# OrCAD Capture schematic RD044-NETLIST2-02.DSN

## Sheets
1 4: size A3
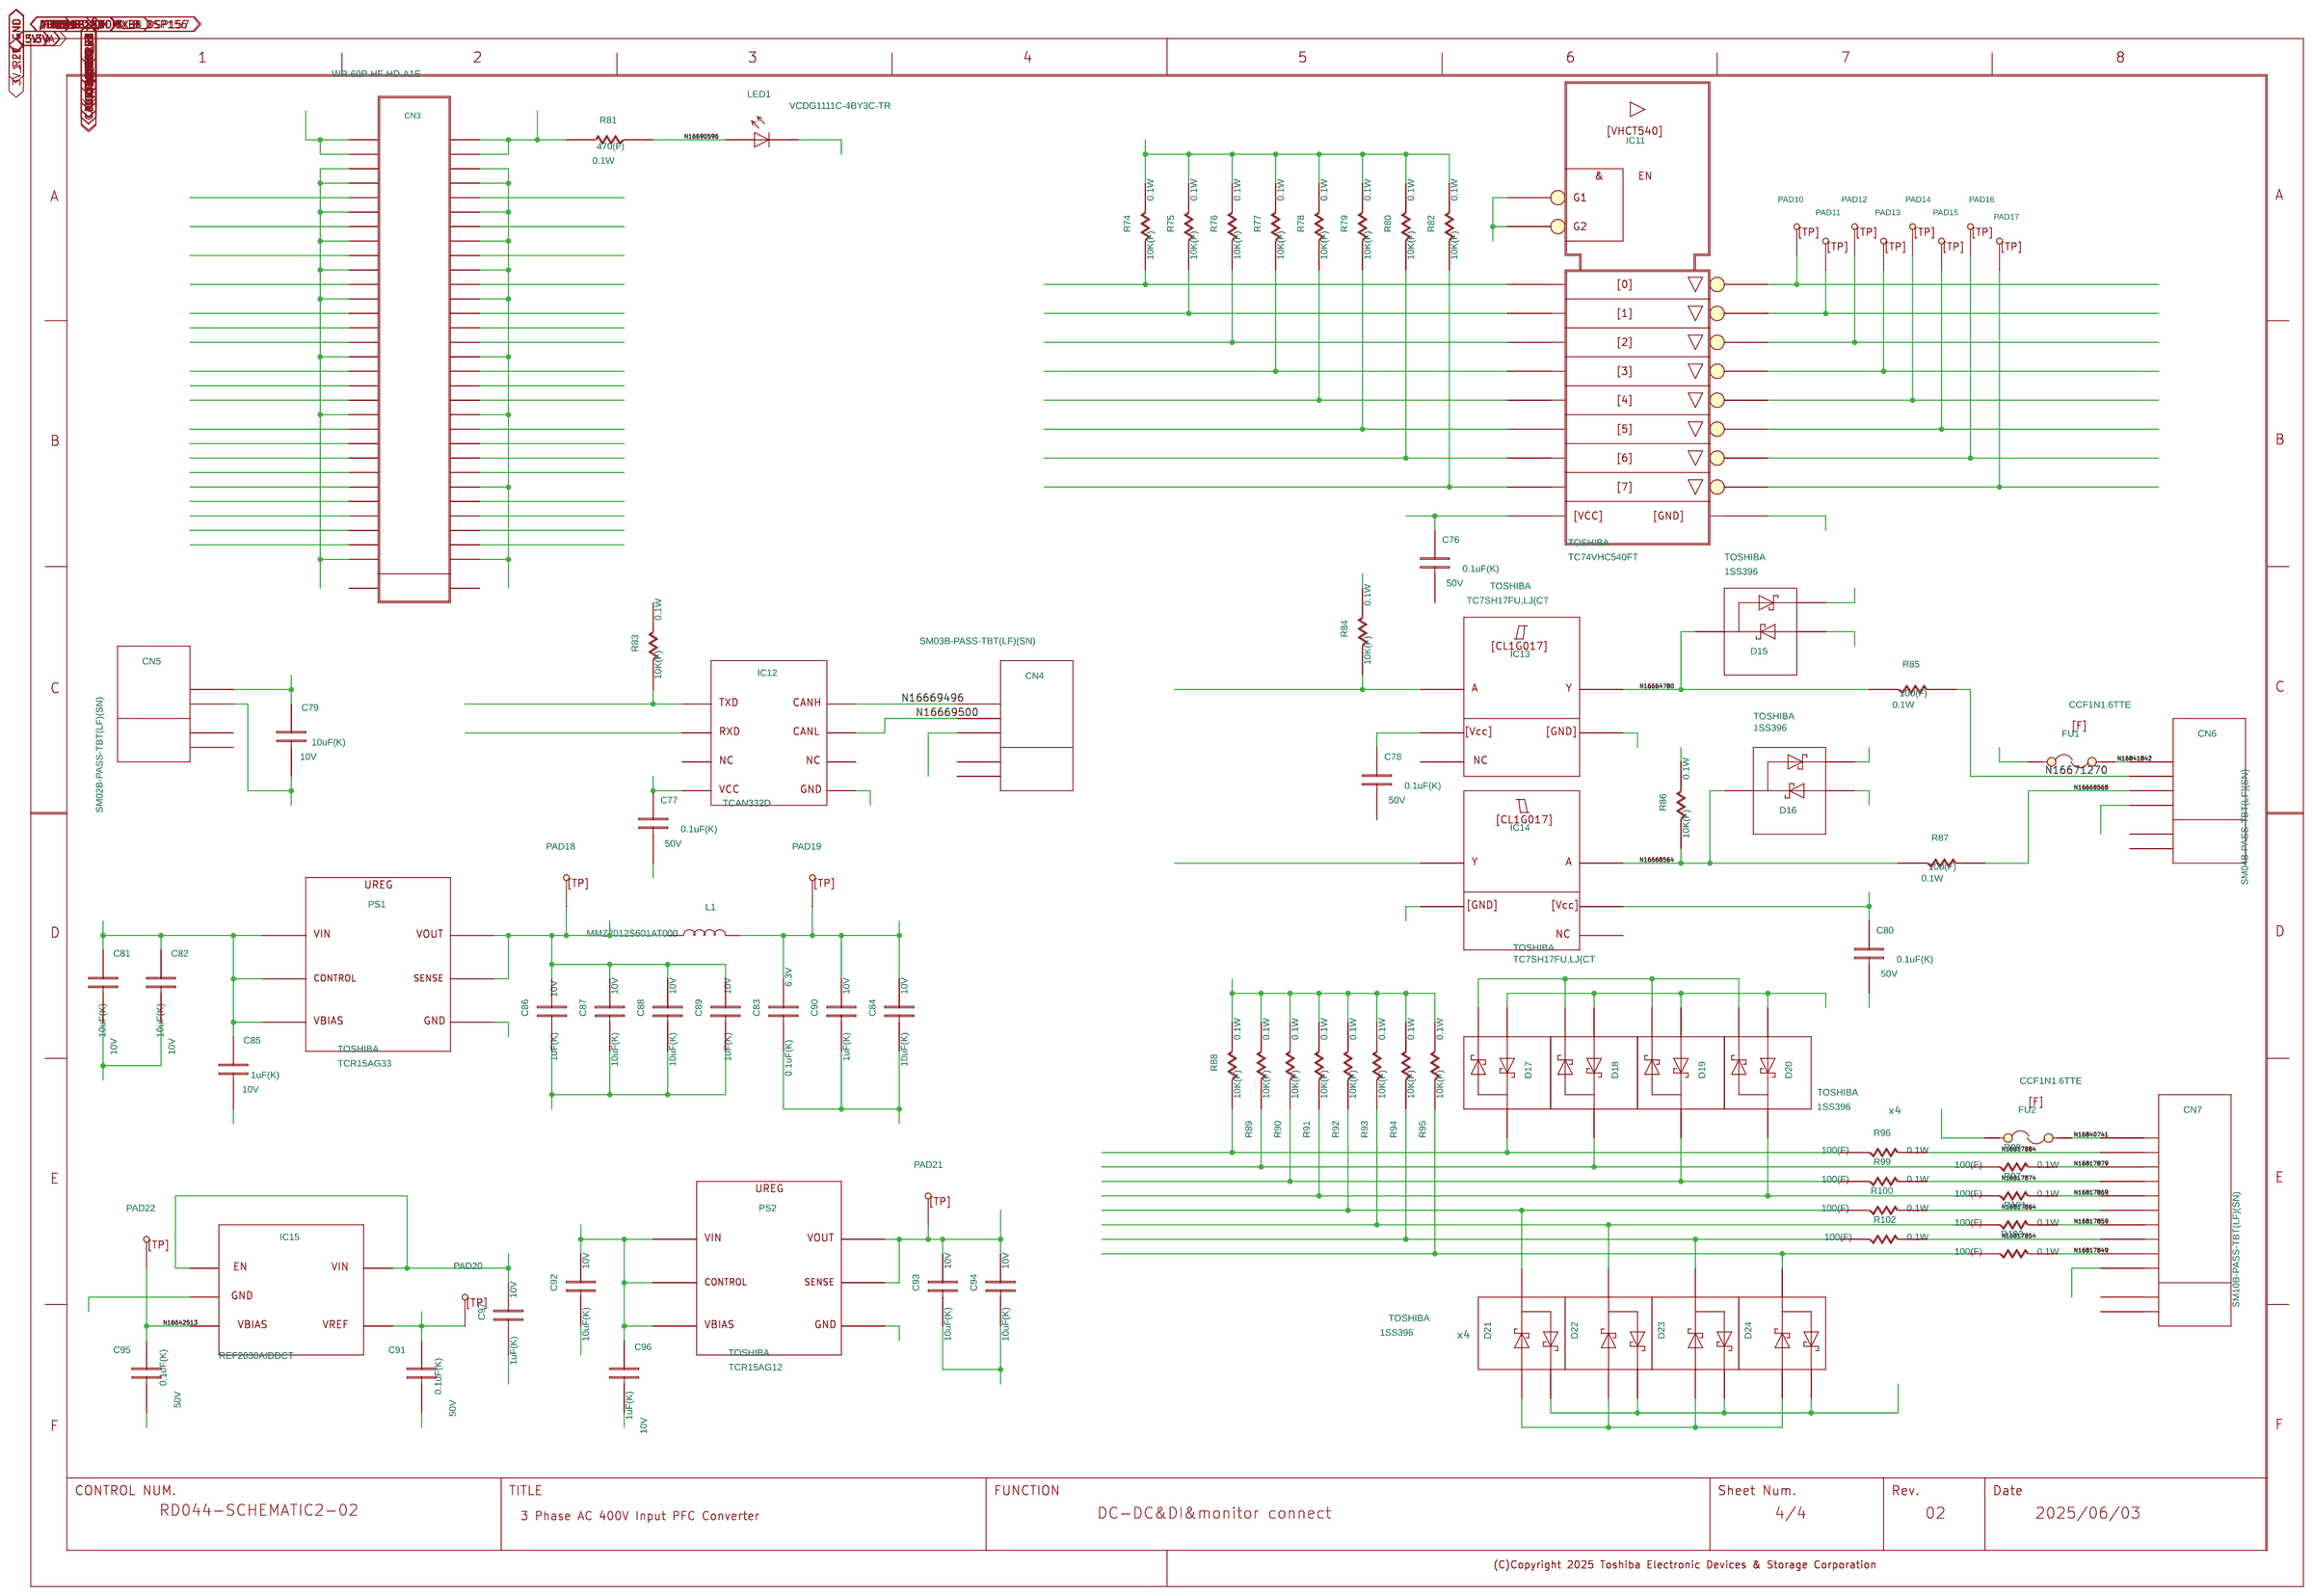
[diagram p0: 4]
2 3: size A3
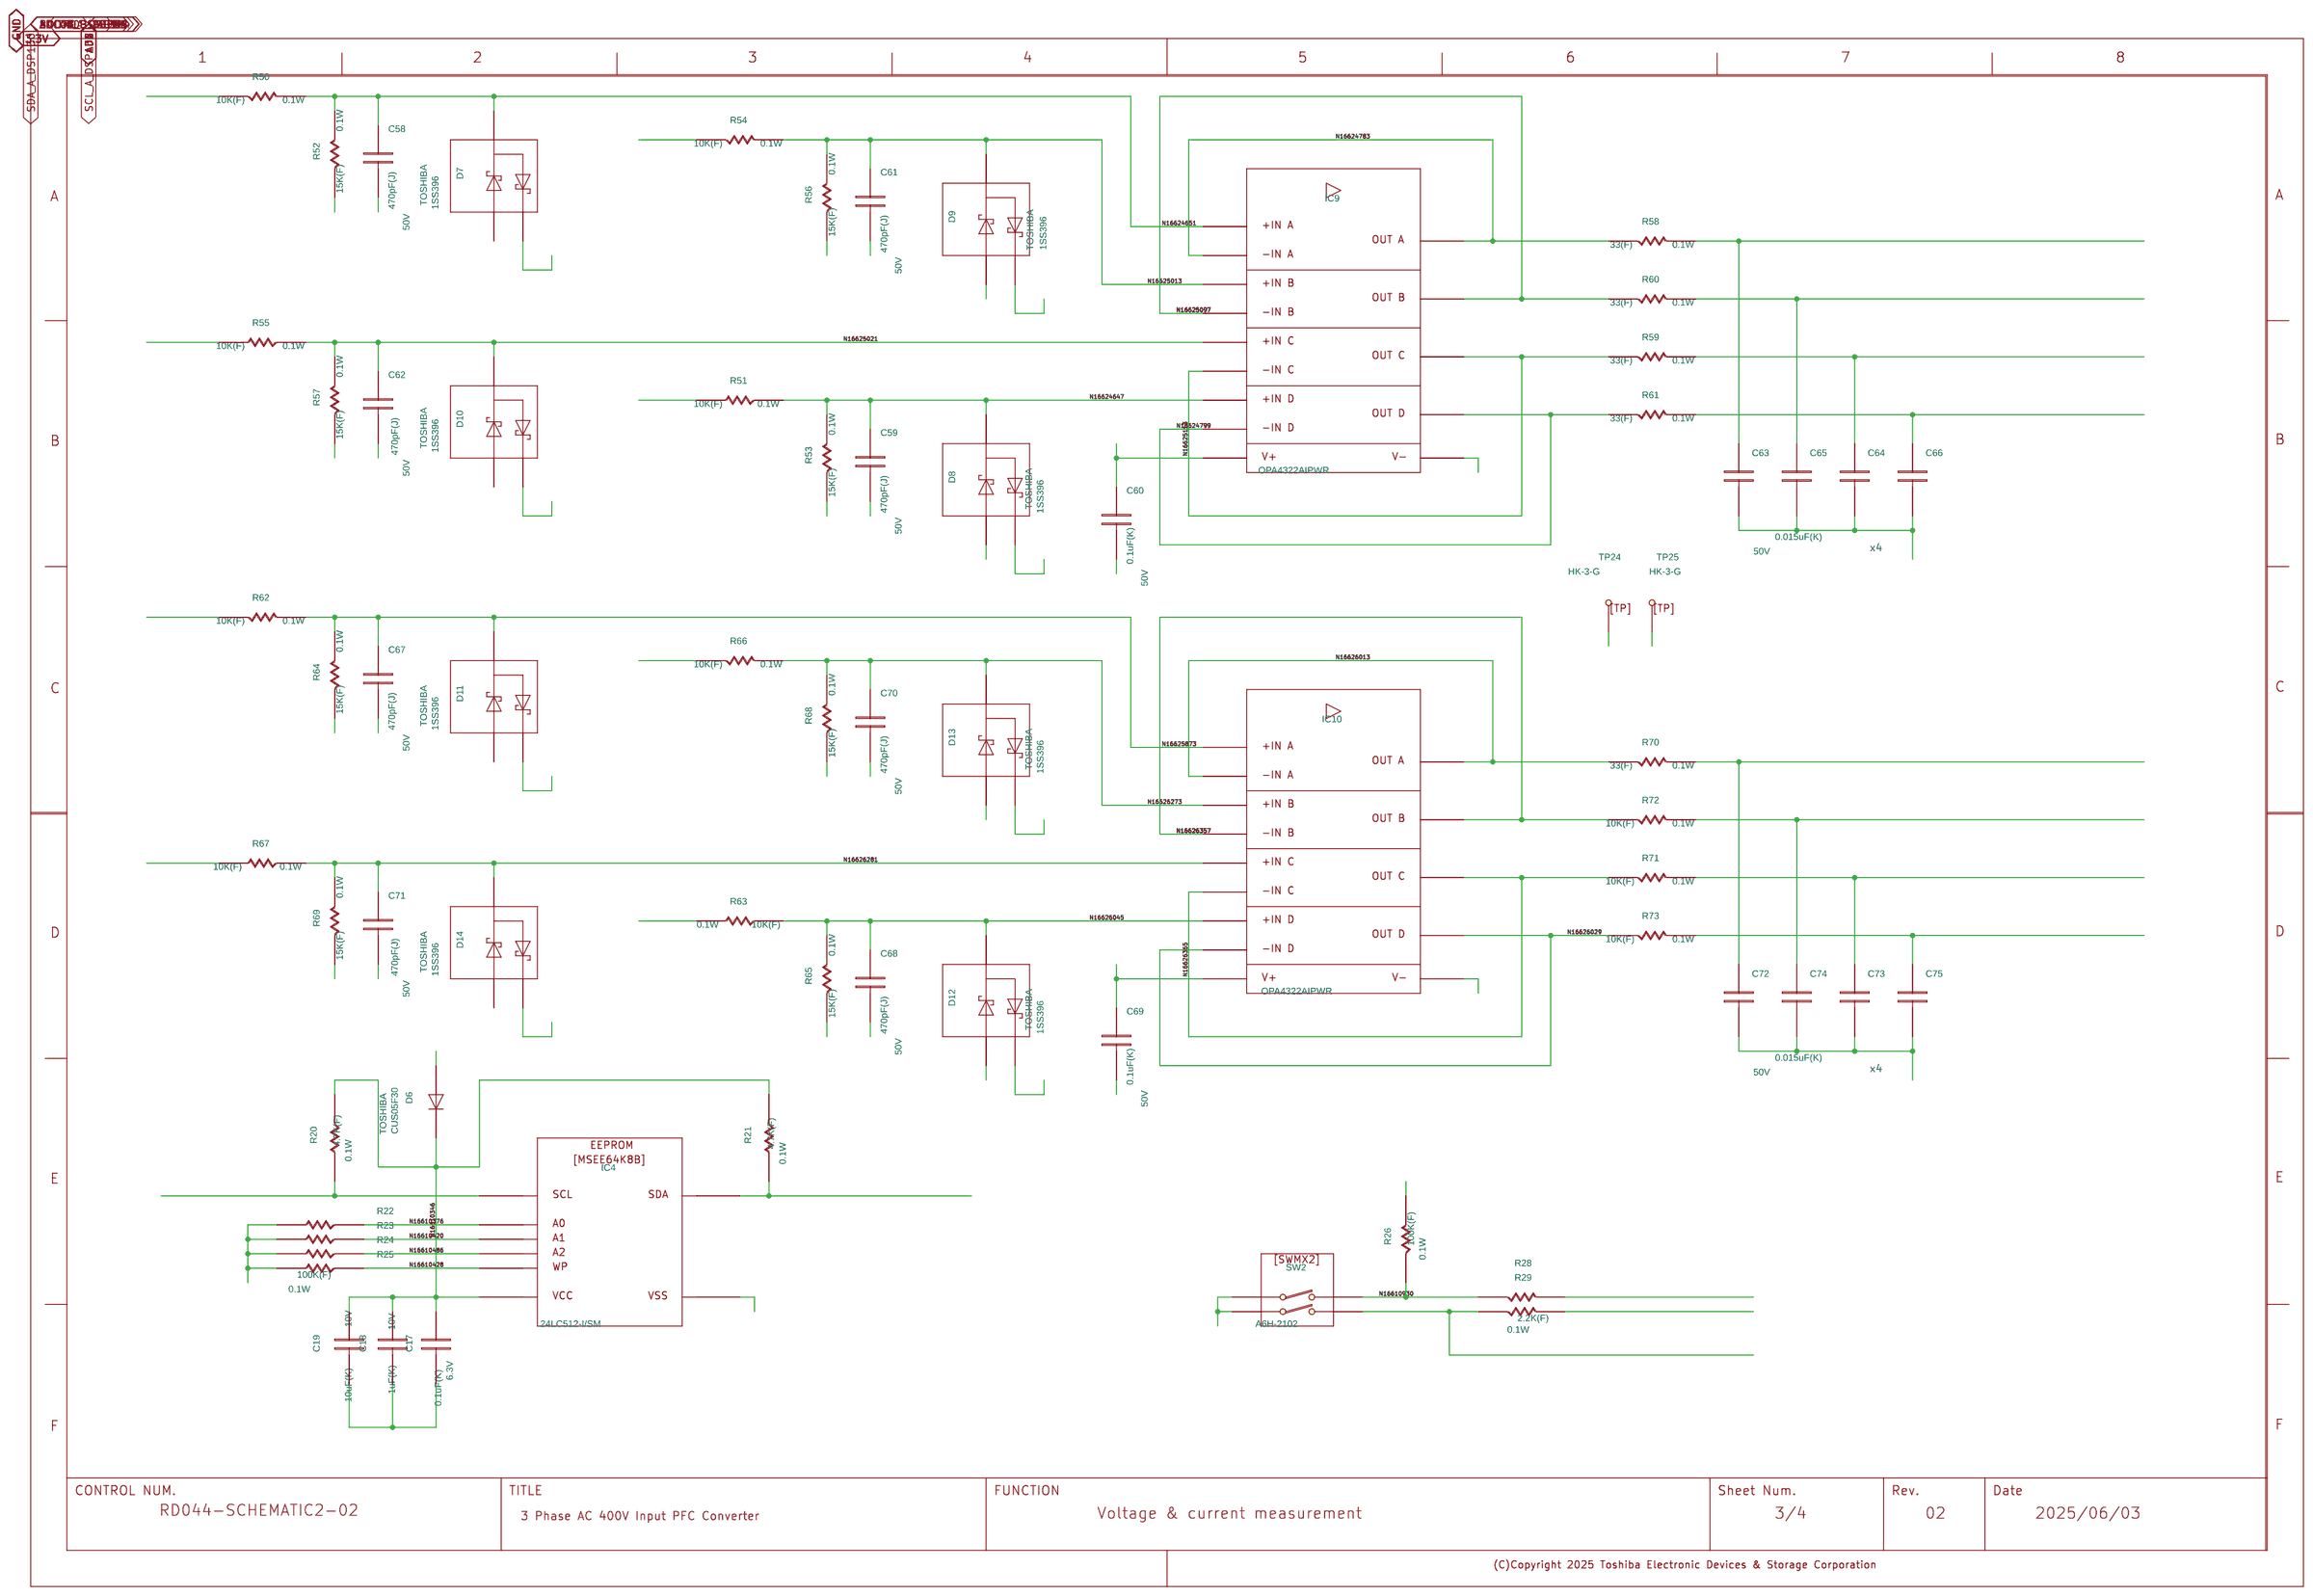
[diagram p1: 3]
3 2: size A3
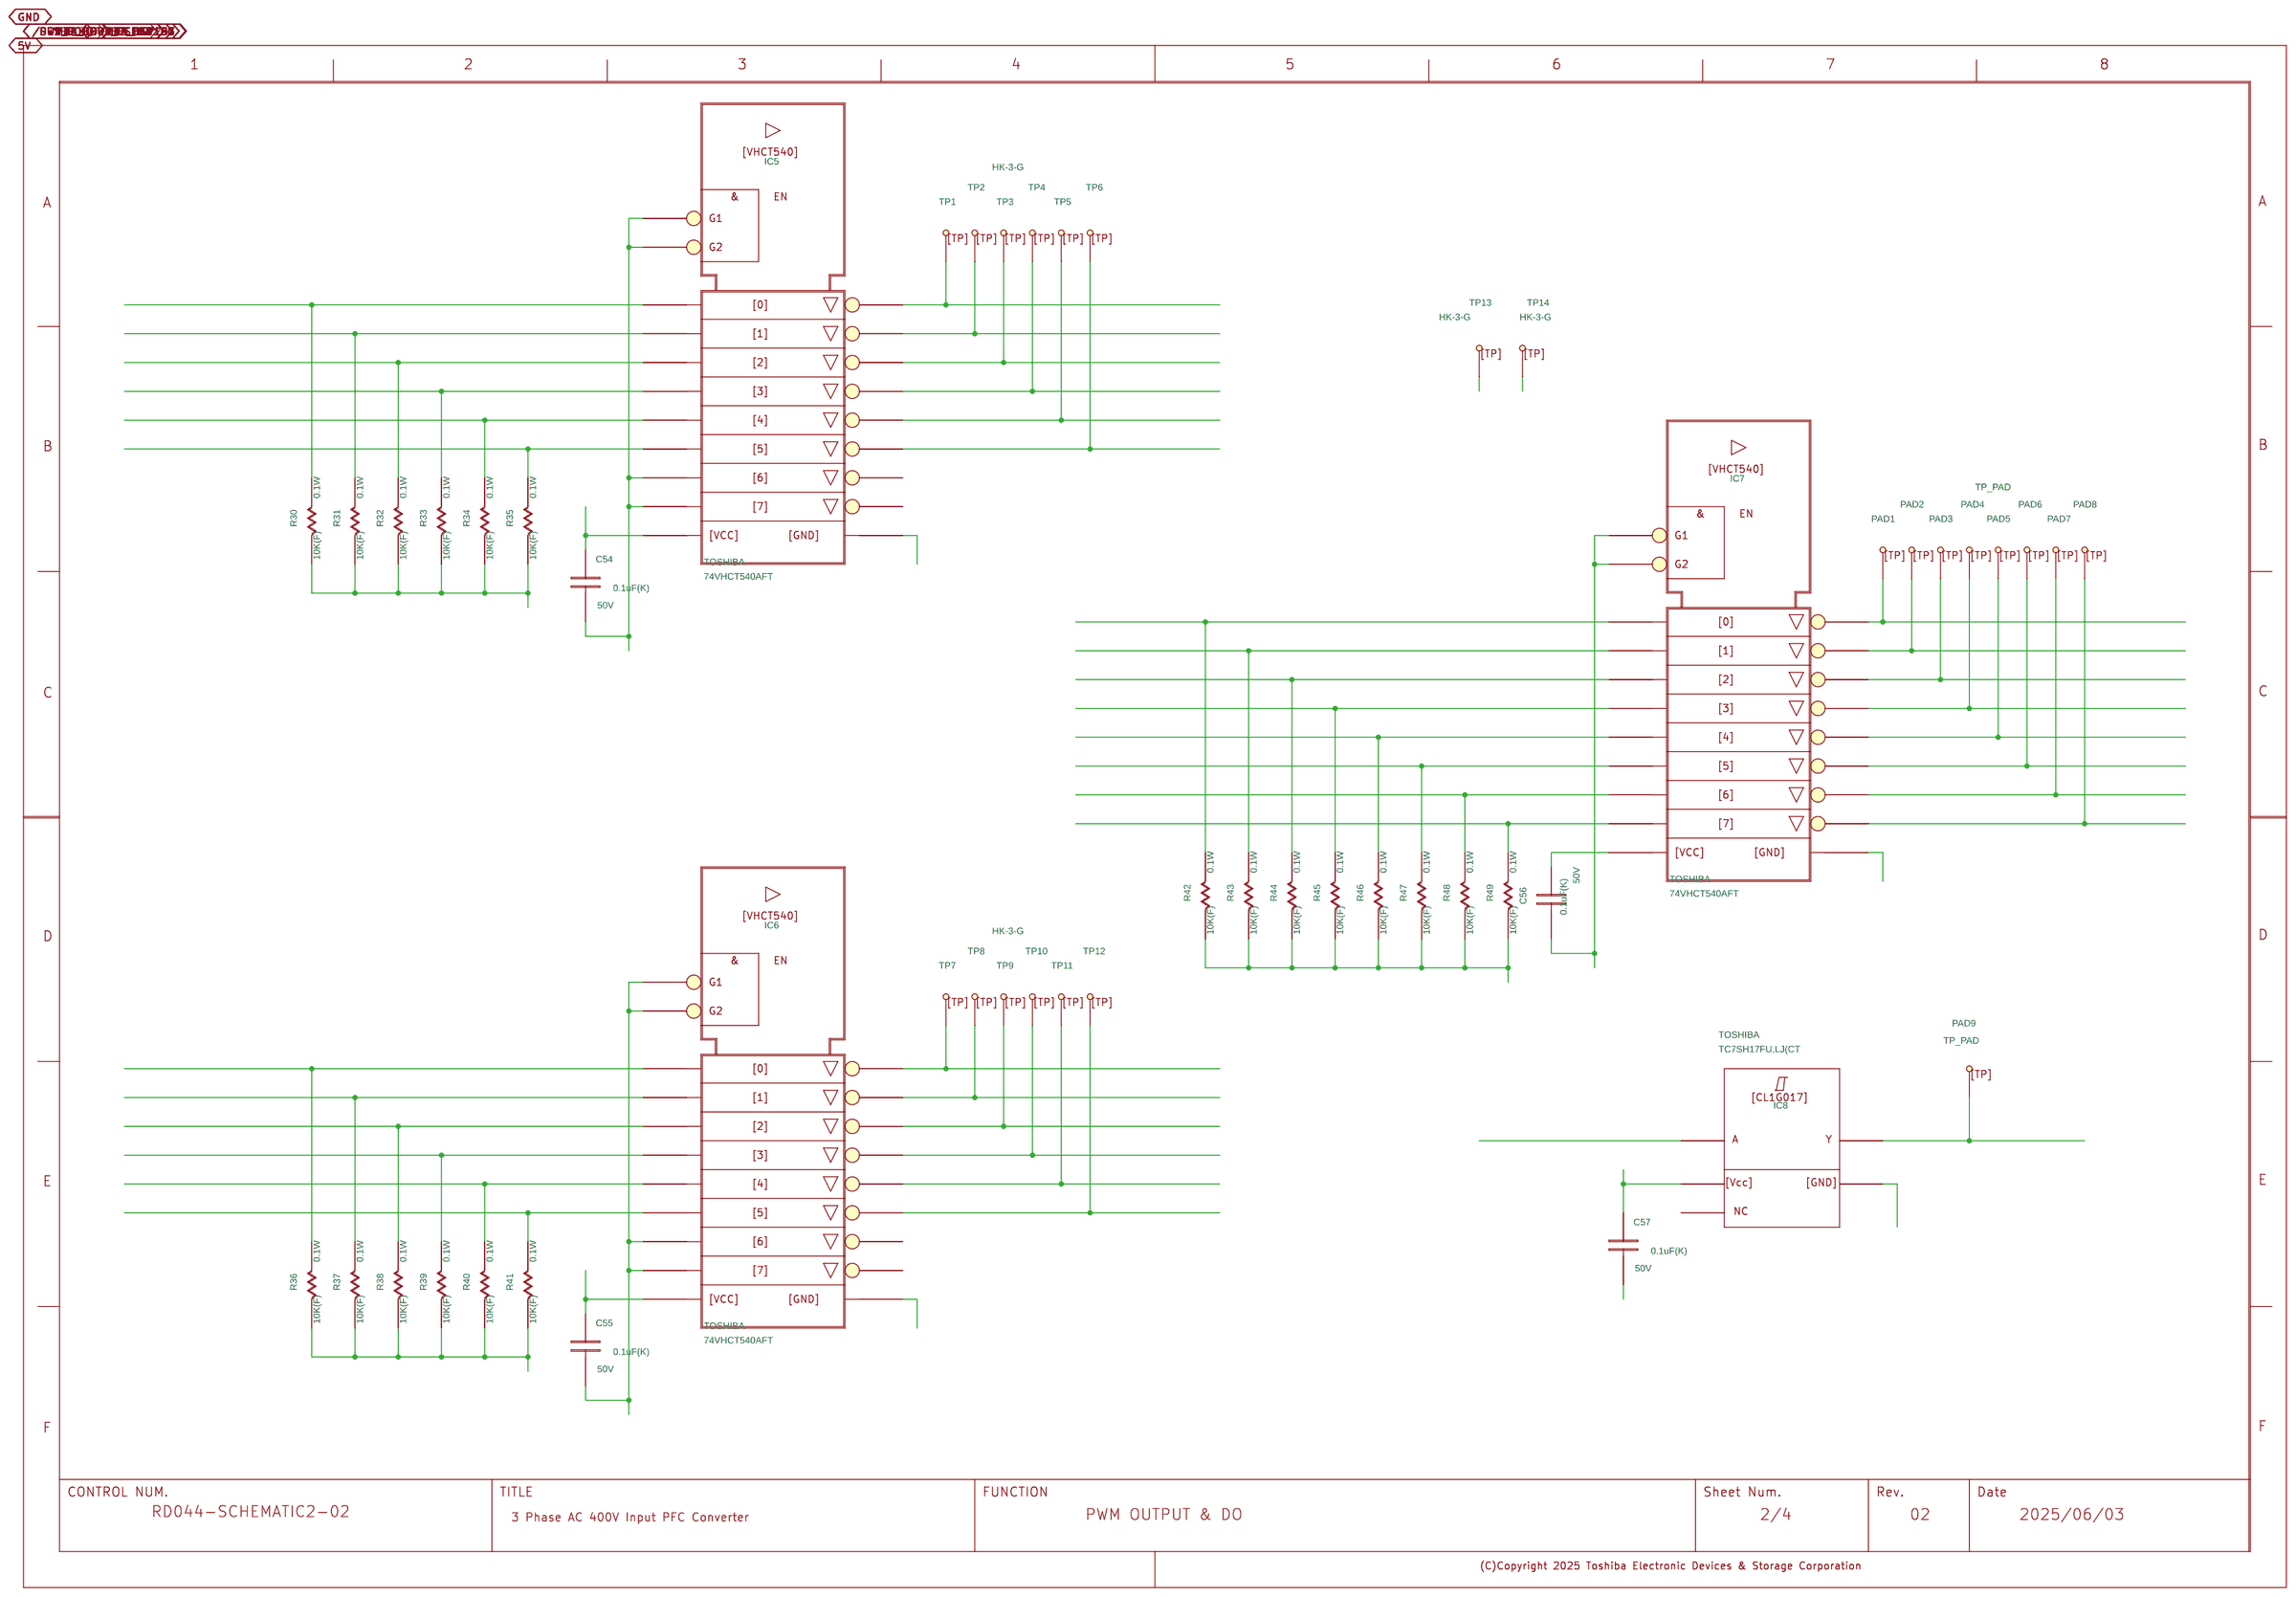
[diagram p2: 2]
4 1: size A3
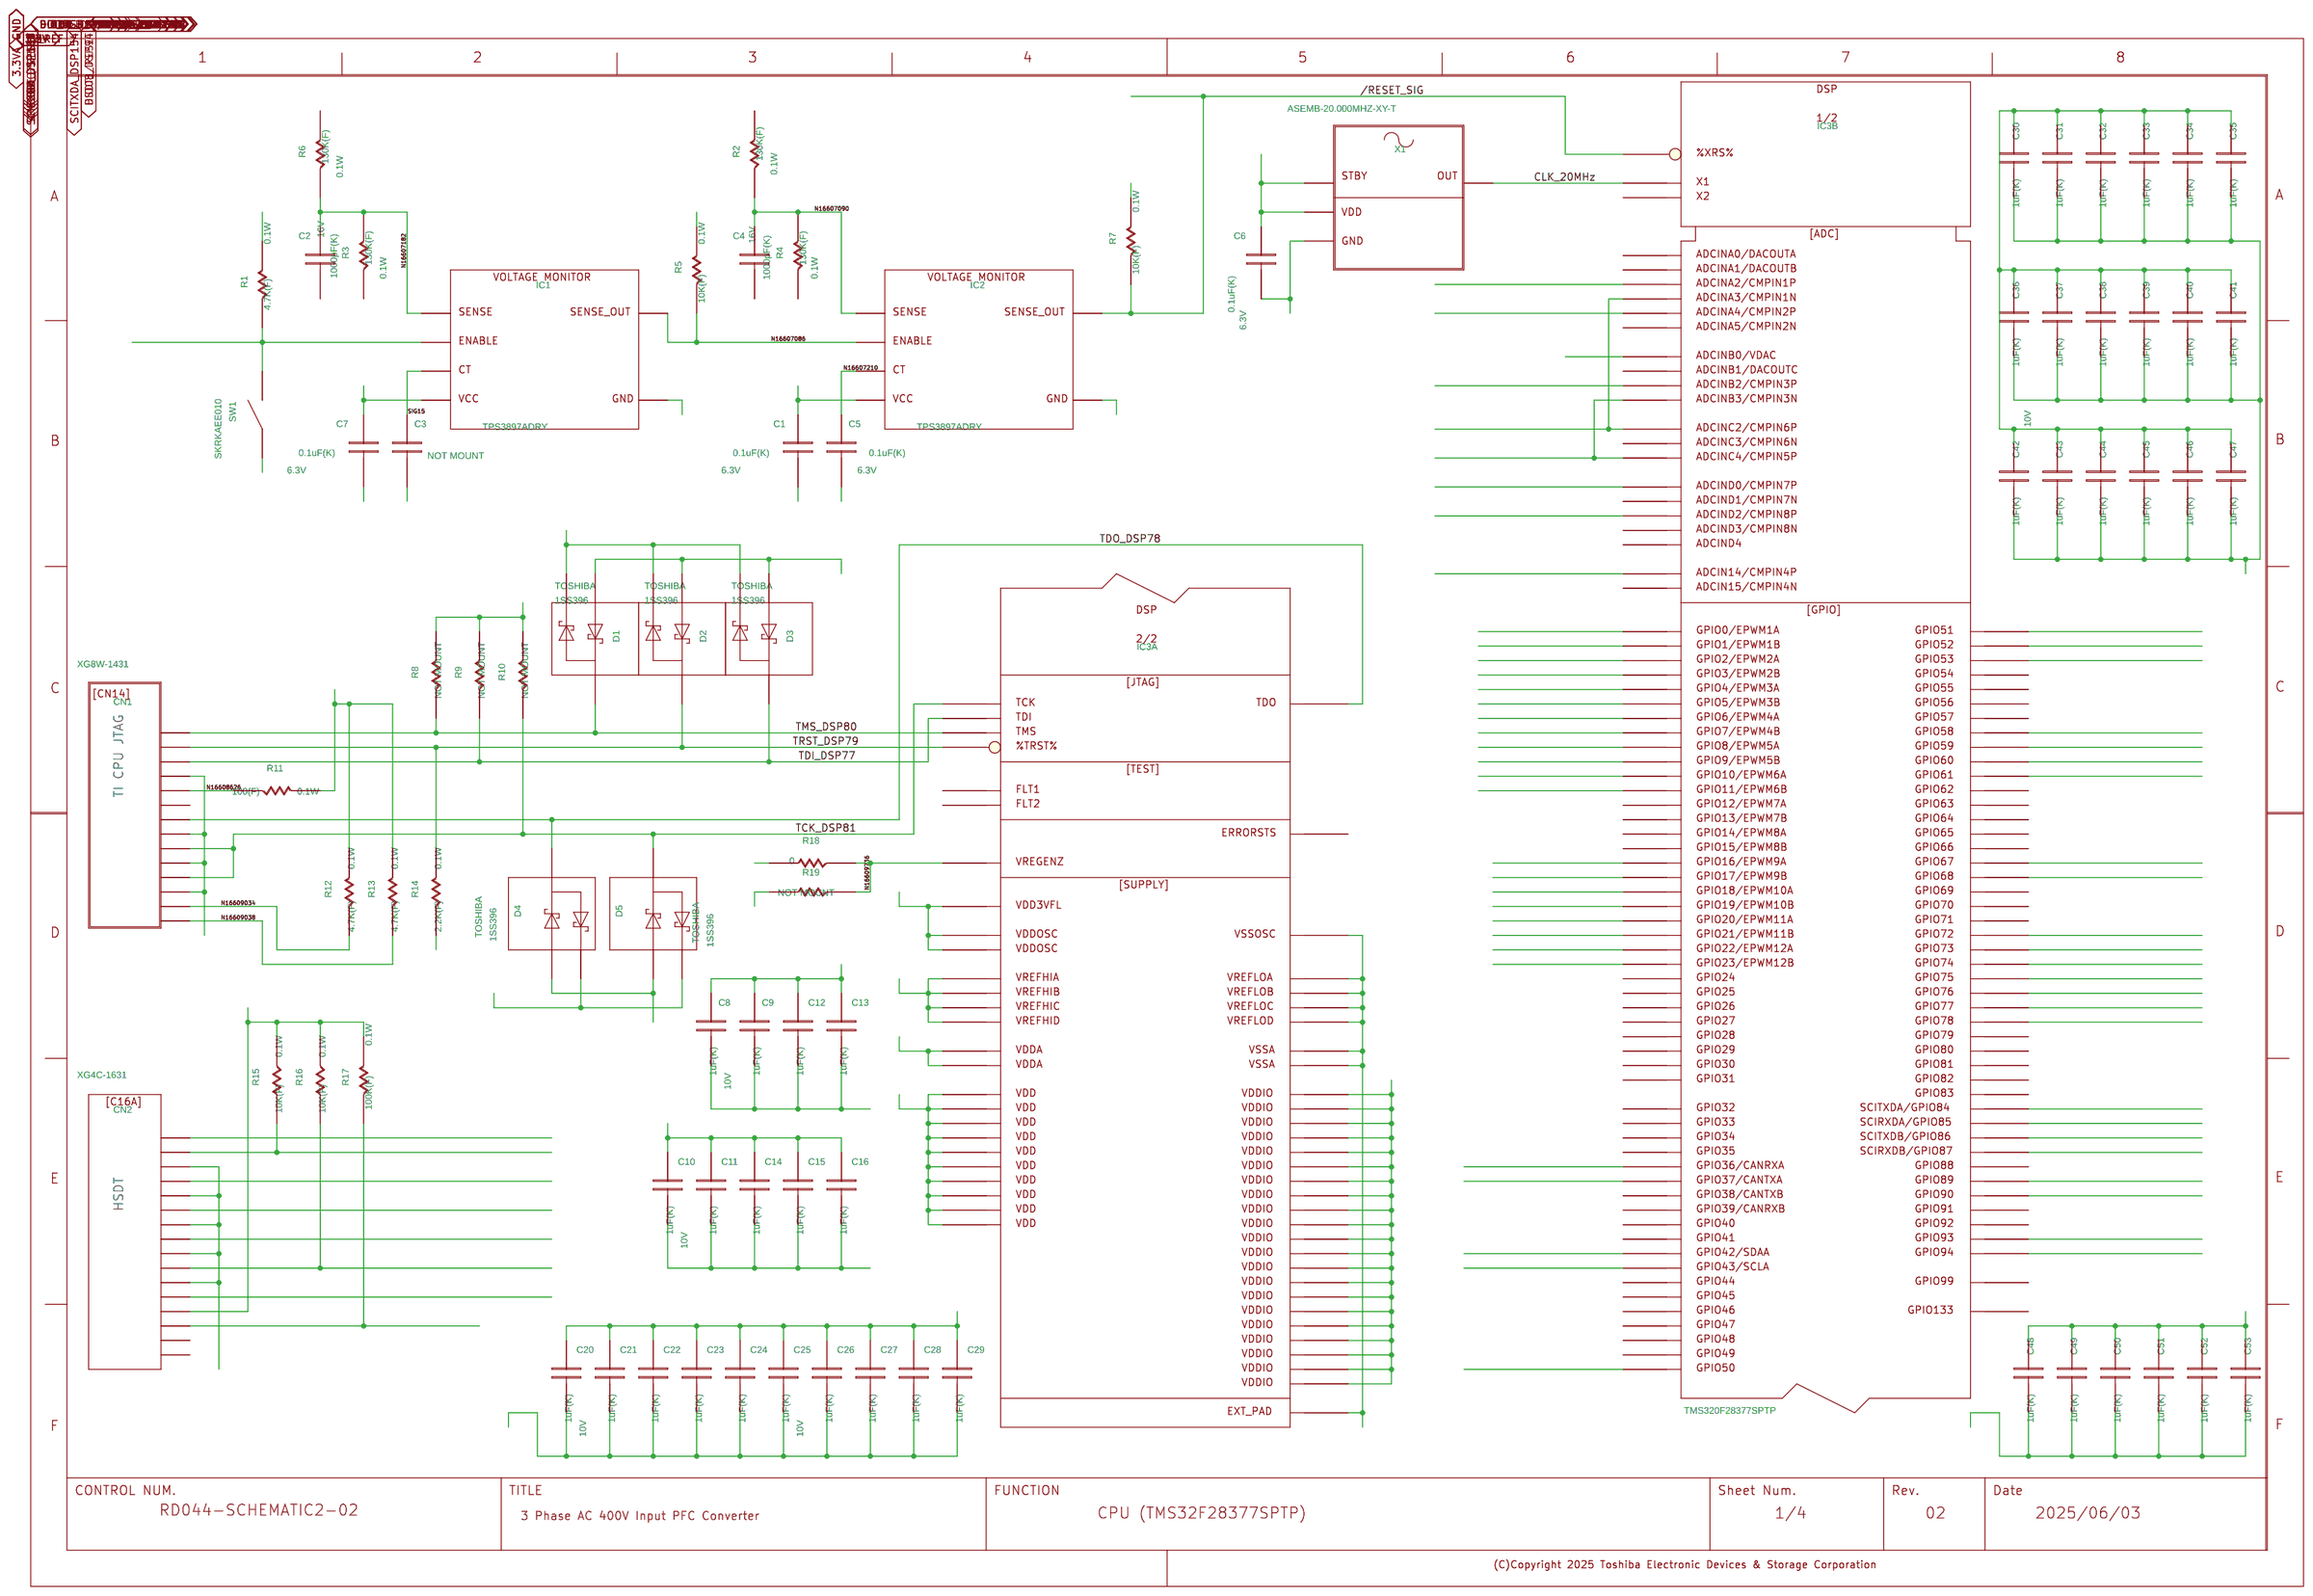
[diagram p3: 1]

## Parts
sheet 1
C1  C
C2  C
C3  C
C4  C
C5  C
C6  C
C7  C
C8  C
C9  C
C10  C
C11  C
C12  C
C13  C
C14  C
C15  C
C16  C
C20  C
C21  C
C22  C
C23  C
C24  C
C25  C
C26  C
C27  C
C28  C
C29  C
C30  C
C31  C
C32  C
C33  C
C34  C
C35  C
C36  C
C37  C
C38  C
C39  C
C40  C
C41  C
C42  C
C43  C
C44  C
C45  C
C46  C
C47  C
C48  C
C49  C
C50  C
C51  C
C52  C
C53  C
CN1  CN14
CN2  C16A
D1  1SS396
D2  1SS396
D3  1SS396
D4  1SS396
D5  1SS396
IC1  TPS3897
IC2  TPS3897
IC3  U320F28377_1  (sections A,B)
R1  R
R2  R
R3  R
R4  R
R5  R
R6  R
R7  R
R8  R
R9  R
R10  R
R11  R
R12  R
R13  R
R14  R
R15  R
R16  R
R17  R
R18  R
R19  R
SW1  SW
U?#3  WAKU_DEF100_2018
X1  ASEMB
sheet 2
C54  C
C55  C
C56  C
C57  C
IC5  VHC540
IC6  VHC540
IC7  VHC540
IC8  CL1G017
PAD1  TP
PAD2  TP
PAD3  TP
PAD4  TP
PAD5  TP
PAD6  TP
PAD7  TP
PAD8  TP
PAD9  TP
R30  R
R31  R
R32  R
R33  R
R34  R
R35  R
R36  R
R37  R
R38  R
R39  R
R40  R
R41  R
R42  R
R43  R
R44  R
R45  R
R46  R
R47  R
R48  R
R49  R
TP1  TP
TP2  TP
TP3  TP
TP4  TP
TP5  TP
TP6  TP
TP7  TP
TP8  TP
TP9  TP
TP10  TP
TP11  TP
TP12  TP
TP13  TP
TP14  TP
U?#2  WAKU_DEF100_2018
sheet 3
C17  C
C18  C
C19  C
C58  C
C59  C
C60  C
C61  C
C62  C
C63  C
C64  C
C65  C
C66  C
C67  C
C68  C
C69  C
C70  C
C71  C
C72  C
C73  C
C74  C
C75  C
D6  DIODE
D7  1SS396
D8  1SS396
D9  1SS396
D10  1SS396
D11  1SS396
D12  1SS396
D13  1SS396
D14  1SS396
IC4  MSEE64K8B
IC9  OPA4322A
IC10  OPA4322A
R20  R
R21  R
R22  R
R23  R
R24  R
R25  R
R26  R
R28  R
R29  R
R50  R
R51  R
R52  R
R53  R
R54  R
R55  R
R56  R
R57  R
R58  R
R59  R
R60  R
R61  R
R62  R
R63  R
R64  R
R65  R
R66  R
R67  R
R68  R
R69  R
R70  R
R71  R
R72  R
R73  R
SW2  SWMX2
TP24  TP
TP25  TP
U?#1  WAKU_DEF100_2018
sheet 4
C76  C
C77  C
C78  C
C79  C
C80  C
C81  C
C82  C
C83  C
C84  C
C85  C
C86  C
C87  C
C88  C
C89  C
C90  C
C91  C
C92  C
C93  C
C94  C
C95  C
C96  C
C97  C
CN3  WR-60P
CN4  BM03B-PASS
CN5  BM02B-PASS
CN6  BM04B-PASS
CN7  SM10B-PASS
D15  1SS396
D16  1SS396
D17  1SS396
D18  1SS396
D19  1SS396
D20  1SS396
D21  1SS396
D22  1SS396
D23  1SS396
D24  1SS396
FU1  F
FU2  F
IC11  VHC540
IC12  TCAN332D
IC13  CL1G017
IC14  CL1G017
IC15  REF
L1  L
LED1  VCDG1111C
PAD10  TP
PAD11  TP
PAD12  TP
PAD13  TP
PAD14  TP
PAD15  TP
PAD16  TP
PAD17  TP
PAD18  TP
PAD19  TP
PAD20  TP
PAD21  TP
PAD22  TP
PS1  L15AG
PS2  L15AG
R74  R
R75  R
R76  R
R77  R
R78  R
R79  R
R80  R
R81  R
R82  R
R83  R
R84  R
R85  R
R86  R
R87  R
R88  R
R89  R
R90  R
R91  R
R92  R
R93  R
R94  R
R95  R
R96  R
R97  R
R98  R
R99  R
R100  R
R101  R
R102  R
R103  R
U?#4  WAKU_DEF100_2018

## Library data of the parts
C1 C5-C7 C17 C83 = C: CDBNAME: C-GRM155R70J104KA01D; COMP: C-GRM155R70J104KA01D; COMPONENTTYPE: 4; USERCOMPTEXT1: 1005; VAL1: 0.1uF(K); VAL2: 6.3V
C2 C4 = C: CDBNAME: C-GRM188R71C102KA01D; COMP: C-GRM188R71C102KA01D; COMPONENTTYPE: 4; USERCOMPTEXT1: 1608; VAL1: 1000pF(K); VAL2: 16V
C3 = C: CDBNAME: C-1608_NM; COMP: C-1608_NM; COMPONENTTYPE: 4; NOTMOUNT: NOT MOUNT; USERCOMPTEXT1: 1608
C8 C10 C18 C20 C25 C42 C85 C86 C89 C90 C96 C97 = C: CDBNAME: C-GRM188R71A105KA61D; COMP: C-GRM188R71A105KA61D; COMPONENTTYPE: 4; USERCOMPTEXT1: 1608; VAL1: 1uF(K); VAL2: 10V
C9 C11-C16 C21-C24 C26-C41 C43-C53 = C: CDBNAME: C-GRM188R71A105KA61D; COMP: C-GRM188R71A105KA61D; COMPONENTTYPE: 4; VAL1: 1uF(K)
CN1 = CN14: ADSCNVFLAG: ON; CDBNAME: CN-XG8W-1431; COMP: CN-XG8W-1431; COMPONENTTYPE: 4; GCOUNT: 1; MAXGCOUNT: 1; VAL3: XG8W-1431
CN2 = C16A: CDBNAME: CN-XG4C-1631; COMP: CN-XG4C-1631; COMPONENTTYPE: 4; VAL3: XG4C-1631
D1-D5 D7-D24 = 1SS396: CDBNAME: D-1SS396_AK; COMP: D-1SS396_AK; COMPONENTTYPE: 4; USERCOMPTEXT3: TOSHIBA
IC1 IC2 = TPS3897: CDBNAME: IC-TPS3897ADRY; COMP: IC-TPS3897ADRY; COMPONENTTYPE: 4; VAL3: TPS3897ADRY
IC3 = U320F28377_1: CDBNAME: IC-TMS320F28377SPTP; COMP: IC-TMS320F28377SPTP; COMPONENTTYPE: 8; CaptureCellPackProp: U320F28377_1A; FUNCN: TMS320F_2_function; VAL3: TMS320F28377SPTP
R1 R12 R13 R20 R21 = R: CDBNAME: R-ERJ3EKF4701V; COMP: R-ERJ3EKF4701V; COMPONENTTYPE: 4; USERCOMPTEXT1: 1608; VAL1: 4.7K(F); VAL2: 0.1W
R2 = R: CDBNAME: R-ERA3AEB304V; COMP: R-ERA3AEB304V; COMPONENTTYPE: 4; USERCOMPTEXT1: 1608; VAL1: 130K(F); VAL2: 0.1W
R3 = R: CDBNAME: R-ERJ3EKF1003V; COMP: R-ERJ3EKF1003V; COMPONENTTYPE: 4; USERCOMPTEXT1: 1608; VAL1: 130K(F); VAL2: 0.1W
R4 = R: CDBNAME: R-ERA3AEB563V; COMP: R-ERA3AEB563V; COMPONENTTYPE: 4; USERCOMPTEXT1: 1608; VAL1: 130K(F); VAL2: 0.1W
R5 R7 R15 R16 R30-R51 R54 R55 R62 R63 R66 R67 R74-R80 R82-R84 R86 R88-R95 = R: CDBNAME: R-ERJ3EKF1002V; COMP: R-ERJ3EKF1002V; COMPONENTTYPE: 4; USERCOMPTEXT1: 1608; VAL1: 10K(F); VAL2: 0.1W
R6 = R: CDBNAME: R-ERA3AEB134V; COMP: R-ERA3AEB134V; COMPONENTTYPE: 4; USERCOMPTEXT1: 1608; VAL1: 130K(F); VAL2: 0.1W
R8-R10 R19 = R: CDBNAME: R-1608_NM; COMP: R-1608_NM; COMPONENTTYPE: 4; NOTMOUNT: NOT MOUNT; USERCOMPTEXT1: 1608
R11 R85 R87 R96-R103 = R: CDBNAME: R-ERJ3EKF1000V; COMP: R-ERJ3EKF1000V; COMPONENTTYPE: 4; USERCOMPTEXT1: 1608; VAL1: 100(F); VAL2: 0.1W
R14 R28 R29 = R: CDBNAME: R-ERJ3EKF2201V; COMP: R-ERJ3EKF2201V; COMPONENTTYPE: 4; USERCOMPTEXT1: 1608; VAL1: 2.2K(F); VAL2: 0.1W
R17 R22-R26 = R: CDBNAME: R-ERJ3EKF1003V; COMP: R-ERJ3EKF1003V; COMPONENTTYPE: 4; USERCOMPTEXT1: 1608; VAL1: 100K(F); VAL2: 0.1W
R18 = R: CDBNAME: R-RK73Z1JTTD; COMP: R-RK73Z1JTTD; COMPONENTTYPE: 4; VAL1: 0
SW1 = SW: ADSCNVFLAG: ON; CDBNAME: SW-SKRKAEE010; COMP: SW-SKRKAEE010; COMPONENTTYPE: 4; GCOUNT: 1; MAXGCOUNT: 1; VAL3: SKRKAEE010
U?#3 = WAKU_DEF100_2018: COMPONENTTYPE: 2; DATE: 2025/06/03; DRAWINGNUMBER: RD044-SCHEMATIC2-02; FUNCTION: CPU (TMS32F28377SPTP); REVISION: 02; SAVEAREA0: -45080,-4508,463680,304612; SAVECOUNT: 4; SHEETNUMBER: 1/4; SHTSAVECOUNT: 4; TIME: 13:54:34; TITLE: 3 Phase AC 400V Input PFC Converter; UPDATEDATE: 2025.6.3; UPDATETIME: 15:56:23; UPDATEUSER: e5025010
X1 = ASEMB: CDBNAME: X-ASEMB-20.000MHZ-XY-T; COMP: X-ASEMB-20.000MHZ-XY-T; COMPONENTTYPE: 4; VAL3: ASEMB-20.000MHZ-XY-T
C54-C57 C60 C69 C76-C78 C80 C91 C95 = C: CDBNAME: C-GRM188R71H104KA93D; COMP: C-GRM188R71H104KA93D; COMPONENTTYPE: 4; USERCOMPTEXT1: 1608; VAL1: 0.1uF(K); VAL2: 50V
IC5-IC7 = VHC540: CDBNAME: IC-74VHCT540AFT; COMP: IC-74VHCT540AFT; COMPONENTTYPE: 4; USERCOMPTEXT3: TOSHIBA; VAL3: 74VHCT540AFT
IC8 IC13 IC14 = CL1G017: ADSCNVFLAG: ON; CDBNAME: IC-TC7SH17F; COMP: IC-TC7SH17F; COMPONENTTYPE: 4; GCOUNT: 1; MAXGCOUNT: 1; USERCOMPTEXT3: TOSHIBA; VAL1: TC7SH17FU,LJ(CT; VAL3: TC7SH17FU,LJ(CT
PAD1 PAD2 PAD7-PAD10 PAD18-PAD22 = TP: CDBNAME: TP-PAD1.0; COMP: TP-PAD1.0; COMPONENTTYPE: 4; VAL3: TP_PAD
PAD3-PAD6 = TP: CDBNAME: TP-PAD1.0; COMP: TP-PAD1.0; COMPONENTTYPE: 4; VAL3: HK-3-G
TP1-TP14 TP24 TP25 = TP: CDBNAME: TP-HK-3-G; COMP: TP-HK-3-G; COMPONENTTYPE: 4; VAL3: HK-3-G
U?#2 = WAKU_DEF100_2018: COMPONENTTYPE: 2; DATE: 2025/06/03; DRAWINGNUMBER: RD044-SCHEMATIC2-02; FUNCTION: PWM OUTPUT & DO; REVISION: 02; SAVEAREA0: -45080,-4508,463680,304612; SAVECOUNT: 4; SHEETNUMBER: 2/4; SHTSAVECOUNT: 4; TIME: 13:54:34; TITLE: 3 Phase AC 400V Input PFC Converter; UPDATEDATE: 2025.6.3; UPDATETIME: 15:56:23; UPDATEUSER: e5025010
C19 C79 C81 C82 C84 C87 C88 C92-C94 = C: CDBNAME: C-GRM188R61A106KE69D; COMP: C-GRM188R61A106KE69D; COMPONENTTYPE: 4; USERCOMPTEXT1: 1608; VAL1: 10uF(K); VAL2: 10V
C58 C59 C61 C62 C67 C68 C70 C71 = C: CDBNAME: C-GRM1885C1H471JA01D; COMP: C-GRM1885C1H471JA01D; COMPONENTTYPE: 4; USERCOMPTEXT1: 1608; VAL1: 470pF(J); VAL2: 50V
C63-C66 C72-C75 = C: CDBNAME: C-GRM188R11H153KA01D; COMP: C-GRM188R11H153KA01D; COMPONENTTYPE: 4; USERCOMPTEXT1: 1608; VAL1: 0.015uF(K); VAL2: 50V
D6 = DIODE: CDBNAME: D-CUS05F30; COMP: D-CUS05F30; COMPONENTTYPE: 4; USERCOMPTEXT3: TOSHIBA; VAL3: CUS05F30
IC4 = MSEE64K8B: ADSCNVFLAG: ON; CDBNAME: IC-24LC512-I_SM; COMP: IC-24LC512-I_SM; COMPONENTTYPE: 4; GCOUNT: 1; MAXGCOUNT: 1; VAL1: 24LC512-I/SM; VAL3: 24LC512-I/SM
IC9 IC10 = OPA4322A: CDBNAME: IC-OPA4322AIPWR; COMP: IC-OPA4322AIPWR; COMPONENTTYPE: 4; VAL3: OPA4322AIPWR
R52 R53 R56 R57 R64 R65 R68 R69 = R: CDBNAME: R-ERJ3EKF1502V; COMP: R-ERJ3EKF1502V; COMPONENTTYPE: 4; USERCOMPTEXT1: 1608; VAL1: 15K(F); VAL2: 0.1W
R58-R61 R70 = R: CDBNAME: R-ERJ3EKF33R0V; COMP: R-ERJ3EKF33R0V; COMPONENTTYPE: 4; USERCOMPTEXT1: 1608; VAL1: 33(F); VAL2: 0.1W
R71-R73 = R: CDBNAME: R-ERJ3EKF33R0V; COMP: R-ERJ3EKF33R0V; COMPONENTTYPE: 4; USERCOMPTEXT1: 1608; VAL1: 10K(F); VAL2: 0.1W
SW2 = SWMX2: CDBNAME: SW-A6H-2102; COMP: SW-A6H-2102; COMPONENTTYPE: 4; VAL3: A6H-2102
U?#1 = WAKU_DEF100_2018: COMPONENTTYPE: 2; DATE: 2025/06/03; DRAWINGNUMBER: RD044-SCHEMATIC2-02; FUNCTION: Voltage & current measurement; REVISION: 02; SAVEAREA0: -45080,-4508,463680,304612; SAVECOUNT: 4; SHEETNUMBER: 3/4; SHTSAVECOUNT: 6; TIME: 13:54:34; TITLE: 3 Phase AC 400V Input PFC Converter; UPDATEDATE: 2025.6.3; UPDATETIME: 16:01:41; UPDATEUSER: e5025010
CN3 = WR-60P: CDBNAME: CN-WR-60P-HF-HD-A1E; COMP: CN-WR-60P-HF-HD-A1E; COMPONENTTYPE: 4; VAL3: WR-60P-HF-HD-A1E
CN4 = BM03B-PASS: CDBNAME: CN-SM03B-PASS-TBT_LF_SN; COMP: CN-SM03B-PASS-TBT_LF_SN; COMPONENTTYPE: 4; SAVEAREA0: -16737,-296,39143,28727; SAVECOUNT: 24; VAL3: SM03B-PASS-TBT(LF)(SN)
CN5 = BM02B-PASS: CDBNAME: CN-SM02B-PASS-TBT_LF_SN; COMP: CN-SM02B-PASS-TBT_LF_SN; COMPONENTTYPE: 4; SAVEAREA0: -14164,-269,36638,26116; SAVECOUNT: 26; VAL3: SM02B-PASS-TBT(LF)(SN)
CN6 = BM04B-PASS: CDBNAME: CN-SM04B-PASS-TBT_LF_SN; COMP: CN-SM04B-PASS-TBT_LF_SN; COMPONENTTYPE: 4; SAVEAREA0: -19295,-323,41666,31339; SAVECOUNT: 22; VAL3: SM04B-PASS-TBT(LF)(SN)
CN7 = SM10B-PASS: CDBNAME: CN-SM10B-PASS-TBT_LF_SN; COMP: CN-SM10B-PASS-TBT_LF_SN; COMPONENTTYPE: 4; VAL3: SM10B-PASS-TBT(LF)(SN)
FU1 FU2 = F: CDBNAME: FU-CCF1N1.6TTE; COMP: FU-CCF1N1.6TTE; COMPONENTTYPE: 4; VAL3: CCF1N1.6TTE
IC11 = VHC540: CDBNAME: IC-TC74VHC540FT; COMP: IC-TC74VHC540FT; COMPONENTTYPE: 4; USERCOMPTEXT3: TOSHIBA; VAL3: TC74VHC540FT
IC12 = TCAN332D: CDBNAME: IC-TCAN332D; COMP: IC-TCAN332D; COMPONENTTYPE: 4
IC15 = REF: CDBNAME: IC-REF2030AIDDCT; COMP: IC-REF2030AIDDCT; COMPONENTTYPE: 4; VAL3: REF2030AIDDCT
L1 = L: CDBNAME: L-MMZ2012S601AT000; COMP: L-MMZ2012S601AT000; COMPONENTTYPE: 4; VAL3: MMZ2012S601AT000
LED1 = VCDG1111C: CDBNAME: LED-VCDG1111C-4BY3C-TR; COMP: LED-VCDG1111C-4BY3C-TR; COMPONENTTYPE: 4; VAL3: VCDG1111C-4BY3C-TR
PAD11-PAD17 = TP: CDBNAME: TP-PAD1.0; COMP: TP-PAD1.0; COMPONENTTYPE: 4
PS1 = L15AG: CDBNAME: PS-TCR15AG33; COMP: PS-TCR15AG33; COMPONENTTYPE: 4; USERCOMPTEXT3: TOSHIBA; VAL3: TCR15AG33
PS2 = L15AG: CDBNAME: PS-TCR15AG12; COMP: PS-TCR15AG12; COMPONENTTYPE: 4; USERCOMPTEXT3: TOSHIBA; VAL3: TCR15AG12
R81 = R: CDBNAME: R-ERJ3EKF4700V; COMP: R-ERJ3EKF4700V; COMPONENTTYPE: 4; USERCOMPTEXT1: 1608; VAL1: 470(F); VAL2: 0.1W
U?#4 = WAKU_DEF100_2018: COMPONENTTYPE: 2; DATE: 2025/06/03; DRAWINGNUMBER: RD044-SCHEMATIC2-02; FUNCTION: DC-DC&DI&monitor connect; REVISION: 02; SAVEAREA0: -45080,-4508,463680,304612; SAVECOUNT: 4; SHEETNUMBER: 4/4; SHTSAVECOUNT: 6; TIME: 13:54:34; TITLE: 3 Phase AC 400V Input PFC Converter; UPDATEDATE: 2025.6.3; UPDATETIME: 16:01:41; UPDATEUSER: e5025010

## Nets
1.2V: C20.1 C21.1 C22.1 C23.1 C24.1 C25.1 C26.1 C27.1 C28.1 C29.1 C93.1 C94.1 IC3.16 IC3.21 IC3.61 IC3.76 IC3.117 IC3.126 IC3.137 IC3.153 IC3.158 IC3.169 PAD21.1 PS2.A1 PS2.B1 R6.1
3.3V: C1.1 C1.2 C2.2 C3.2 C4.2 C5.2 C6.1 C6.2 C7.1 C7.2 C8.2 C9.2 C10.2 C11.2 C12.2 C13.2 C14.2 C15.2 C16.2 C17.2 C18.2 C19.2 C20.2 C21.2 C22.2 C23.2 C24.2 C25.2 C26.2 C27.2 C28.2 C29.2 C30.1 C30.2 C31.1 C31.2 C32.1 C32.2 C33.1 C33.2 C34.1 C34.2 C35.1 C35.2 C36.1 C36.2 C37.1 C37.2 C38.1 C38.2 C39.1 C39.2 C40.1 C40.2 C41.1 C41.2 C42.1 C42.2 C43.1 C43.2 C44.1 C44.2 C45.1 C45.2 C46.1 C46.2 C47.1 C47.2 C48.1 C48.2 C49.1 C49.2 C50.1 C50.2 C51.1 C51.2 C52.1 C52.2 C53.1 C53.2 C54.2 C55.2 C56.2 C57.2 C58.2 C59.2 C60.1 C60.2 C61.2 C62.2 C63.2 C64.2 C65.2 C66.2 C67.2 C68.2 C69.1 C69.2 C70.2 C71.2 C72.2 C73.2 C74.2 C75.2 C76.1 C76.2 C77.1 C77.2 C78.2 C79.2 C80.1 C80.2 C81.2 C82.2 C83.2 C84.2 C85.2 C86.1 C86.2 C87.1 C87.2 C88.1 C88.2 C89.1 C89.2 C90.2 C91.2 C92.2 C93.2 C94.2 C95.2 C96.2 C97.2 CN1.4 CN1.8 CN1.10 CN1.12 CN2.3 CN2.5 CN2.7 CN2.9 CN2.11 CN2.13 CN3.5 CN3.6 CN3.7 CN3.8 CN3.11 CN3.12 CN3.15 CN3.16 CN3.19 CN3.20 CN3.23 CN3.24 CN3.31 CN3.32 CN3.39 CN3.40 CN3.50 CN3.59 CN3.60 CN4.3 CN5.2 CN6.4 CN7.10 D1.A D1.K D2.A D2.K D3.A D3.K D4.A D4.K D5.A D5.K D6.A D7.A D7.K D8.A D8.K D9.A D9.K D10.A D10.K D11.A D11.K D12.A D12.K D13.A D13.K D14.A D14.K D15.A D16.A D17.A D17.K D18.A D18.K D19.A D19.K D20.A D20.K D21.A D21.K D22.A D22.K D23.A D23.K D24.A D24.K FU2.2 IC1.2 IC1.6 IC2.2 IC2.6 IC3.3 IC3.11 IC3.15 IC3.20 IC3.26 IC3.32 IC3.33 IC3.34 IC3.50 IC3.51 IC3.52 IC3.62 IC3.68 IC3.72 IC3.75 IC3.82 IC3.88 IC3.91 IC3.99 IC3.106 IC3.114 IC3.116 IC3.120 IC3.122 IC3.125 IC3.127 IC3.138 IC3.147 IC3.152 IC3.159 IC3.168 IC3.P1 IC4.4 IC5.1 IC5.8 IC5.9 IC5.10 IC5.19 IC6.1 IC6.8 IC6.9 IC6.10 IC6.19 IC7.1 IC7.10 IC7.19 IC8.3 IC9.4 IC9.11 IC10.4 IC10.11 IC11.1 IC11.10 IC11.19 IC11.20 IC12.2 IC12.3 IC13.3 IC14.3 IC14.5 IC15.2 L1.2 LED1.K PAD18.1 PS1.A1 PS1.B1 PS1.C1 PS2.C1 R1.1 R2.1 R3.2 R4.2 R5.1 R7.1 R8.1 R9.1 R10.1 R11.1 R12.1 R13.1 R14.2 R15.2 R16.2 R17.1 R18.1 R19.1 R22.1 R23.1 R24.1 R25.1 R26.1 R30.2 R31.2 R32.2 R33.2 R34.2 R35.2 R36.2 R37.2 R38.2 R39.2 R40.2 R41.2 R42.2 R43.2 R44.2 R45.2 R46.2 R47.2 R48.2 R49.2 R52.2 R53.2 R56.2 R57.2 R64.2 R65.2 R68.2 R69.2 R83.1 R84.1 R88.1 R89.1 R90.1 R91.1 R92.1 R93.1 R94.1 R95.1 SW1.1 SW2.1 SW2.2 TP13.1 TP14.1 TP24.1 TP25.1 X1.1 X1.2 X1.4
3.3VA: C8.1 C9.1 C12.1 C13.1 C83.1 C84.1 C90.1 IC3.36 IC3.54 L1.1 PAD19.1
3V_REF: C10.1 C11.1 C14.1 C15.1 C16.1 C91.1 IC3.35 IC3.37 IC3.46 IC3.53 IC3.55 IC15.5 PAD20.1
5V: C54.1 C55.1 C56.1 C57.1 C78.1 C79.1 C81.1 C82.1 C85.1 C92.1 C96.1 C97.1 CN3.1 CN3.2 CN3.3 CN3.4 CN5.1 D15.K D16.K FU1.2 IC5.20 IC6.20 IC7.20 IC8.5 IC13.5 IC15.3 IC15.4 PS1.A2 PS1.B2 PS1.C2 PS2.A2 PS2.B2 PS2.C2 R74.1 R75.1 R76.1 R77.1 R78.1 R79.1 R80.1 R81.1 R82.1 R86.1
/DI0_BI: CN3.51 IC11.2 R74.2
/DI1_BI: CN3.52 IC11.3 R75.2
/DI2_BI: CN3.53 IC11.4 R76.2
/DI3_BI: CN3.54 IC11.5 R77.2
/DI4_BI: CN3.55 IC11.6 R78.2
/DI5_BI: CN3.56 IC11.7 R79.2
/DI6_BI: CN3.57 IC11.8 R80.2
/DI7_BI: CN3.58 IC11.9 R82.2
/DO0_BO: CN3.41 IC7.11 PAD8.1
/DO1_BO: CN3.42 IC7.12 PAD7.1
/DO2_BO: CN3.43 IC7.13 PAD6.1
/DO3_BO: CN3.44 IC7.14 PAD5.1
/DO4_BO: CN3.45 IC7.15 PAD4.1
/DO5_BO: CN3.46 IC7.16 PAD3.1
/DO6_BO: CN3.47 IC7.17 PAD2.1
/DO7_BO: CN3.48 IC7.18 PAD1.1
/PWM1A_BO: CN3.25 IC5.13 TP6.1
/PWM1B_BO: CN3.26 IC5.14 TP5.1
/PWM2A_BO: CN3.27 IC5.15 TP4.1
/PWM2B_BO: CN3.28 IC5.16 TP3.1
/PWM3A_BO: CN3.29 IC5.17 TP2.1
/PWM3B_BO: CN3.30 IC5.18 TP1.1
/PWM4A_BO: CN3.33 IC6.13 TP12.1
/PWM4B_BO: CN3.34 IC6.14 TP11.1
/PWM5A_BO: CN3.35 IC6.15 TP10.1
/PWM5B_BO: CN3.36 IC6.16 TP9.1
/PWM6A_BO: CN3.37 IC6.17 TP8.1
/PWM6B_BO: CN3.38 IC6.18 TP7.1
/RESET_BO: CN3.49 IC8.4 PAD9.1
/RESET_SIG: IC2.4 IC3.124 IC8.2 R7.2
AD0: CN3.9 R50.2
AD1: CN3.10 R54.2
AD2: CN3.13 R55.1
AD3: CN3.14 R51.1
AD4: CN3.17 R62.2
AD5: CN3.18 R66.2
AD6: CN3.21 R67.1
AD7: CN3.22 R63.1
ADC01_P_DSP41: C63.1 IC3.41 R58.1
ADC02_P_DSP39: C65.1 IC3.39 R60.1
ADC03_P_DSP48: C64.1 IC3.48 R59.1
ADC04_P_DSP44: C66.1 IC3.44 R61.1
ADC05_P_DSP31: C72.1 IC3.31 IC3.40 R70.1
ADC06_P_DSP29: C74.1 IC3.29 IC3.49 R72.1
ADC07_P_DSP56: C73.1 IC3.56 R71.1
ADC08_P_DSP58: C75.1 IC3.58 R73.1
BOOT1_DSP: CN2.14 R17.2 R29.2 SW2.3
BOOT1_DSP139: IC3.139 R29.1
CANRX_A_DSP83: IC3.83 IC12.4
CANTX_A_DSP84: IC3.84 IC12.1 R83.2
CLK_20MHz: IC3.123 X1.3
DI0_DSP132: IC3.132 IC11.18 PAD10.1
DI1_DSP133: IC3.133 IC11.17 PAD11.1
DI2_DSP140: IC3.140 IC11.16 PAD12.1
DI3_DSP141: IC3.141 IC11.15 PAD13.1
DI4_DSP142: IC3.142 IC11.14 PAD14.1
DI5_DSP143: IC3.143 IC11.13 PAD15.1
DI6_DSP144: IC3.144 IC11.12 PAD16.1
DI7_DSP145: IC3.145 IC11.11 PAD17.1
DIO08_DSP94: D17.K/A IC3.94 R88.2 R96.2
DIO09_DSP95: D18.K/A IC3.95 R89.2 R98.2
DIO10_DSP96: D19.K/A IC3.96 R90.2 R99.2
DIO11_DSP97: D20.K/A IC3.97 R91.2 R97.2
DIO12_DSP171: D21.K/A IC3.171 R92.2 R100.2
DIO13_DSP172: D22.K/A IC3.172 R93.2 R101.2
DIO14_DSP175: D23.K/A IC3.175 R94.2 R102.2
DIO15_DSP176: D24.K/A IC3.176 R95.2 R103.2
DO0_DSP8: IC3.8 IC7.9 R49.1
DO1_DSP9: IC3.9 IC7.8 R48.1
DO2_DSP10: IC3.10 IC7.7 R47.1
DO3_DSP12: IC3.12 IC7.6 R46.1
DO4_DSP13: IC3.13 IC7.5 R45.1
DO5_DSP14: IC3.14 IC7.4 R44.1
DO6_DSP22: IC3.22 IC7.3 R43.1
DO7_DSP23: IC3.23 IC7.2 R42.1
HSDT_/RESET: CN2.12 IC1.1 R1.2 SW1.2
PWM1A_DSP160: IC3.160 IC5.7 R35.1
PWM1B_DSP161: IC3.161 IC5.6 R34.1
PWM2A_DSP162: IC3.162 IC5.5 R33.1
PWM2B_DSP163: IC3.163 IC5.4 R32.1
PWM3A_DSP164: IC3.164 IC5.3 R31.1
PWM3B_DSP165: IC3.165 IC5.2 R30.1
PWM4A_DSP166: IC3.166 IC6.7 R41.1
PWM4B_DSP167: IC3.167 IC6.6 R40.1
PWM5A_DSP18: IC3.18 IC6.5 R39.1
PWM5B_DSP19: IC3.19 IC6.4 R38.1
PWM6A_DSP1: IC3.1 IC6.3 R37.1
PWM6B_DSP2: IC3.2 IC6.2 R36.1
SCIRX_B_DSP157: IC3.157 IC14.4
SCIRXDA_DSP155: CN2.2 IC3.155 R15.1
SCITX_B_DSP156: IC3.156 IC13.2 R84.2
SCITXDA_DSP154: CN2.1 IC3.154 R28.1
SCL_A_DSP131: IC3.131 IC4.6 R20.1
SDA_A_DSP130: IC3.130 IC4.5 R21.1
SIG15: C3.1 IC1.5
SPISTEA_DSP107: CN2.8 IC3.107
SSCK_DSP105: CN2.6 IC3.105
SSI_DSP104: CN2.10 IC3.104 R16.1
SSO_DSP103: CN2.4 IC3.103
TCK_DSP81: CN1.9 CN1.11 D5.K/A IC3.81 R10.2
TDI_DSP77: CN1.3 D3.K/A IC3.77 R9.2
TDO_DSP78: CN1.7 D4.K/A IC3.78
TMS_DSP80: CN1.1 D1.K/A IC3.80 R8.2
TRST_DSP79: CN1.2 D2.K/A IC3.79 R14.1
N16607086: IC1.4 IC2.1 R5.2
N16607090: C4.1 IC2.3 R2.2 R4.1
N16607182: C2.1 IC1.3 R3.1 R6.2
N16607210: C5.1 IC2.5
N16608626: CN1.5 R11.2
N16609034: CN1.13 R12.2
N16609038: CN1.14 R13.2
N16609736: IC3.119 R18.2 R19.2
N16610346: C17.1 C18.1 C19.1 D6.K IC4.8 R20.2 R21.2
N16610376: IC4.1 R22.2
N16610420: IC4.2 R23.2
N16610428: IC4.7 R25.2
N16610486: IC4.3 R24.2
N16610930: R26.2 R28.2 SW2.4
N16624647: C59.1 D8.K/A IC9.12 R51.2 R53.1
N16624651: C58.1 D7.K/A IC9.3 R50.1 R52.1
N16624783: IC9.1 IC9.2 R58.2
N16624799: IC9.13 IC9.14 R61.2
N16625013: C61.1 D9.K/A IC9.5 R54.1 R56.1
N16625021: C62.1 D10.K/A IC9.10 R55.2 R57.1
N16625097: IC9.6 IC9.7 R60.2
N16625113: IC9.8 IC9.9 R59.2
N16625873: C67.1 D11.K/A IC10.3 R62.1 R64.1
N16626013: IC10.1 IC10.2 R70.2
N16626029: IC10.13 IC10.14 R73.2
N16626045: C68.1 D12.K/A IC10.12 R63.2 R65.1
N16626273: C70.1 D13.K/A IC10.5 R66.1 R68.1
N16626281: C71.1 D14.K/A IC10.10 R67.2 R69.1
N16626357: IC10.6 IC10.7 R72.2
N16626365: IC10.8 IC10.9 R71.2
N16642513: C95.1 IC15.1 PAD22.1
N16664780: D15.K/A IC13.4 R85.2
N16668564: D16.K/A IC14.2 R86.2 R87.2
N16668568: CN6.3 R87.1
N16669496: CN4.1 IC12.7
N16669500: CN4.2 IC12.6
N16671270: CN6.2 R85.1
N16690596: LED1.A R81.2
N16817849: CN7.9 R103.1
N16817854: CN7.8 R102.1
N16817859: CN7.7 R101.1
N16817864: CN7.6 R100.1
N16817869: CN7.5 R97.1
N16817874: CN7.4 R99.1
N16817879: CN7.3 R98.1
N16817884: CN7.2 R96.1
N16840741: CN7.1 FU2.1
N16841842: CN6.1 FU1.1

Not connected (* = marked no-connect by the designer): CN1 6; CN2 15 16; CN3 NC1 NC2; CN4 PAD1 PAD2; CN5 PAD1 PAD2; CN6 PAD1 PAD2; CN7 PAD1 PAD2; IC3 4 5 6 7 17 24 25 27 28 30 38 42 43 45 47 57 59 60 63 64 65 66 67 69 70 71 73 74 85 86 87 89 90 92 93 98 100 101 102 108 109 110 111 112 113 115 118 121 128 129 134 135 136 146 148 149 150 151 170 173 174; IC5 11 12; IC6 11 12; IC8 1; IC12 5 8; IC13 1; IC14 1

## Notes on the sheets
sheet 1
- x4
- x4
sheet 2
- x4
- x4
sheet 4
- TI CPU JTAG
- HSDT
